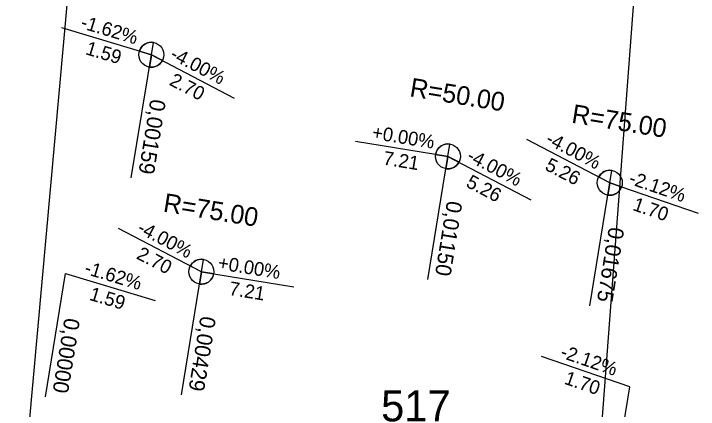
# Model space of a CAD drawing. Extents: x -743186.9 to -743133.1, y -1127113.3 to -1127042.8.
# Drawn here: x -743182.5 to -743160.56, y -1127090.61 to -1127077.93 of the extents above; entities that cross this region are included whole.
import ezdxf

# ---------------------------------------------------------------- set-up
doc = ezdxf.new("R2010")
doc.units = 0
for name, color, linetype in [('bublina_fialová_čára_tenká', 7, 'Continuous'), ('SKLONOVNIKY', 7, 'Continuous'), ('Vrstva 60', 7, 'Continuous')]:
    doc.layers.add(name, color=color, linetype=linetype)

# ---------------------------------------------------------------- blocks, each defined once
blk = doc.blocks.new('AeccTickCircle')
blk.add_circle((0, 0), 0.5)

msp = doc.modelspace()

# ---------------------------------------------------------------- linework, layer by layer
at = {"layer": 'bublina_fialová_čára_tenká'}
for p, q in [((-743160.679, -1127051.634), (-743164.286, -1127099.423)), ((-743179.562, -1127064.096), (-743182.5, -1127096.45))]:
    msp.add_line(p, q, dxfattribs=at)
at = {"layer": 'SKLONOVNIKY'}
for p, q in [((-743178.088, -1127079.247), (-743180.961, -1127078.386)), ((-743178.731, -1127083.195), (-743178.023, -1127078.853)), ((-743178.088, -1127079.247), (-743175.428, -1127080.636)), ((-743163.394, -1127083.35), (-743166.053, -1127081.961)), ((-743168.582, -1127082.505), (-743171.543, -1127082.023)), ((-743169.225, -1127086.453), (-743168.517, -1127082.11)), ((-743168.582, -1127082.505), (-743165.922, -1127083.894)), ((-743164.037, -1127087.298), (-743163.33, -1127082.955)), ((-743163.394, -1127083.35), (-743160.557, -1127084.326)), ((-743176.483, -1127086.201), (-743179.142, -1127084.812)), ((-743177.126, -1127090.149), (-743176.418, -1127085.806)), ((-743181.483, -1127090.206), (-743180.84, -1127086.258)), ((-743180.84, -1127086.258), (-743177.967, -1127087.12)), ((-743176.483, -1127086.201), (-743173.522, -1127086.683)), ((-743162.751, -1127089.893), (-743165.588, -1127088.917)), ((-743163.394, -1127093.841), (-743162.751, -1127089.893))]:
    msp.add_line(p, q, dxfattribs=at)
for points in [[(-743178.471, -1127079.132), (-743178.088, -1127079.247), (-743178.023, -1127078.853)], [(-743177.733, -1127079.432), (-743178.088, -1127079.247), (-743178.152, -1127079.642)], [(-743168.977, -1127082.441), (-743168.582, -1127082.505), (-743168.517, -1127082.11)], [(-743168.227, -1127082.69), (-743168.582, -1127082.505), (-743168.646, -1127082.9)], [(-743163.749, -1127083.164), (-743163.394, -1127083.35), (-743163.33, -1127082.955)], [(-743163.016, -1127083.48), (-743163.394, -1127083.35), (-743163.458, -1127083.744)], [(-743176.837, -1127086.016), (-743176.483, -1127086.201), (-743176.418, -1127085.806)], [(-743176.088, -1127086.265), (-743176.483, -1127086.201), (-743176.547, -1127086.596)]]:
    msp.add_lwpolyline(points, dxfattribs=at)
for centre, start, end in [((-743178.088, -1127079.247), 80.752, 163.3077), ((-743178.088, -1127079.247), 260.752, 332.4271), ((-743168.582, -1127082.505), 80.752, 170.752), ((-743168.582, -1127082.505), 260.752, 332.4271), ((-743163.394, -1127083.35), 80.752, 152.4271), ((-743163.394, -1127083.35), 260.752, 341.0149), ((-743176.483, -1127086.201), 80.752, 152.4271), ((-743176.483, -1127086.201), 260.752, 350.752)]:
    msp.add_arc(centre, 0.4, start, end, dxfattribs=at)

# ---------------------------------------------------------------- block references
at = {"layer": 'SKLONOVNIKY', "xscale": 0.8, "yscale": 0.7999999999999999, "rotation": 80.75200331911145}
for p in [(-743178.088, -1127079.247), (-743168.582, -1127082.505), (-743163.394, -1127083.35), (-743176.483, -1127086.201)]:
    msp.add_blockref('AeccTickCircle', p, dxfattribs=at)

# ---------------------------------------------------------------- texts
at = {"layer": 'SKLONOVNIKY'}
for s, height, rotation, p in [('-1.62%', 0.44, 343.3077, (-743180.382, -1127078.386)), ('1.59', 0.44, 343.3077, (-743180.222, -1127079.225)), ('-4.00%', 0.44, 332.4271, (-743177.519, -1127079.357)), ('2.70', 0.44, 332.4271, (-743177.541, -1127080.2)), ('R=50.00', 0.6, 350.752, (-743169.831, -1127080.575)), ('0,00159', 0.5, 260.752, (-743178.114, -1127080.647)), ('R=75.00', 0.6, 350.752, (-743164.643, -1127081.42)), ('+0.00%', 0.44, 350.752, (-743171.037, -1127081.937)), ('-4.00%', 0.44, 332.4271, (-743165.484, -1127082.071)), ('7.21', 0.44, 350.752, (-743170.677, -1127082.763)), ('-4.00%', 0.44, 332.4271, (-743168.013, -1127082.615)), ('5.26', 0.44, 332.4271, (-743165.504, -1127082.915)), ('-2.12%', 0.44, 341.0149, (-743162.815, -1127083.373)), ('5.26', 0.44, 332.4271, (-743168.032, -1127083.459)), ('R=75.00', 0.6, 350.752, (-743177.732, -1127084.271)), ('1.70', 0.44, 341.0149, (-743162.688, -1127084.218)), ('0,01150', 0.5, 260.752, (-743168.609, -1127083.907)), ('-4.00%', 0.44, 332.4271, (-743178.573, -1127084.922)), ('0,01675', 0.5, 260.752, (-743163.42, -1127084.746)), ('2.70', 0.44, 332.4271, (-743178.595, -1127085.765)), ('+0.00%', 0.44, 350.752, (-743175.977, -1127086.115)), ('-1.62%', 0.44, 343.3077, (-743180.261, -1127086.258)), ('7.21', 0.44, 350.752, (-743175.617, -1127086.941)), ('1.59', 0.44, 343.3077, (-743180.101, -1127087.097)), ('0,00429', 0.5, 260.752, (-743176.509, -1127087.6)), ('0,00000', 0.5, 260.752, (-743180.867, -1127087.66)), ('-2.12%', 0.44, 341.0149, (-743165.009, -1127088.94)), ('1.70', 0.44, 341.0149, (-743164.882, -1127089.785))]:
    msp.add_text(s, height=height, rotation=rotation, dxfattribs=at).set_placement(p)
at = {"layer": 'Vrstva 60'}
msp.add_text('517', height=1, dxfattribs=at).set_placement((-743170.724, -1127090.996))

doc.saveas('drawing.dxf')
